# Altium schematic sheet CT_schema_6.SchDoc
size 274 x 160 mm
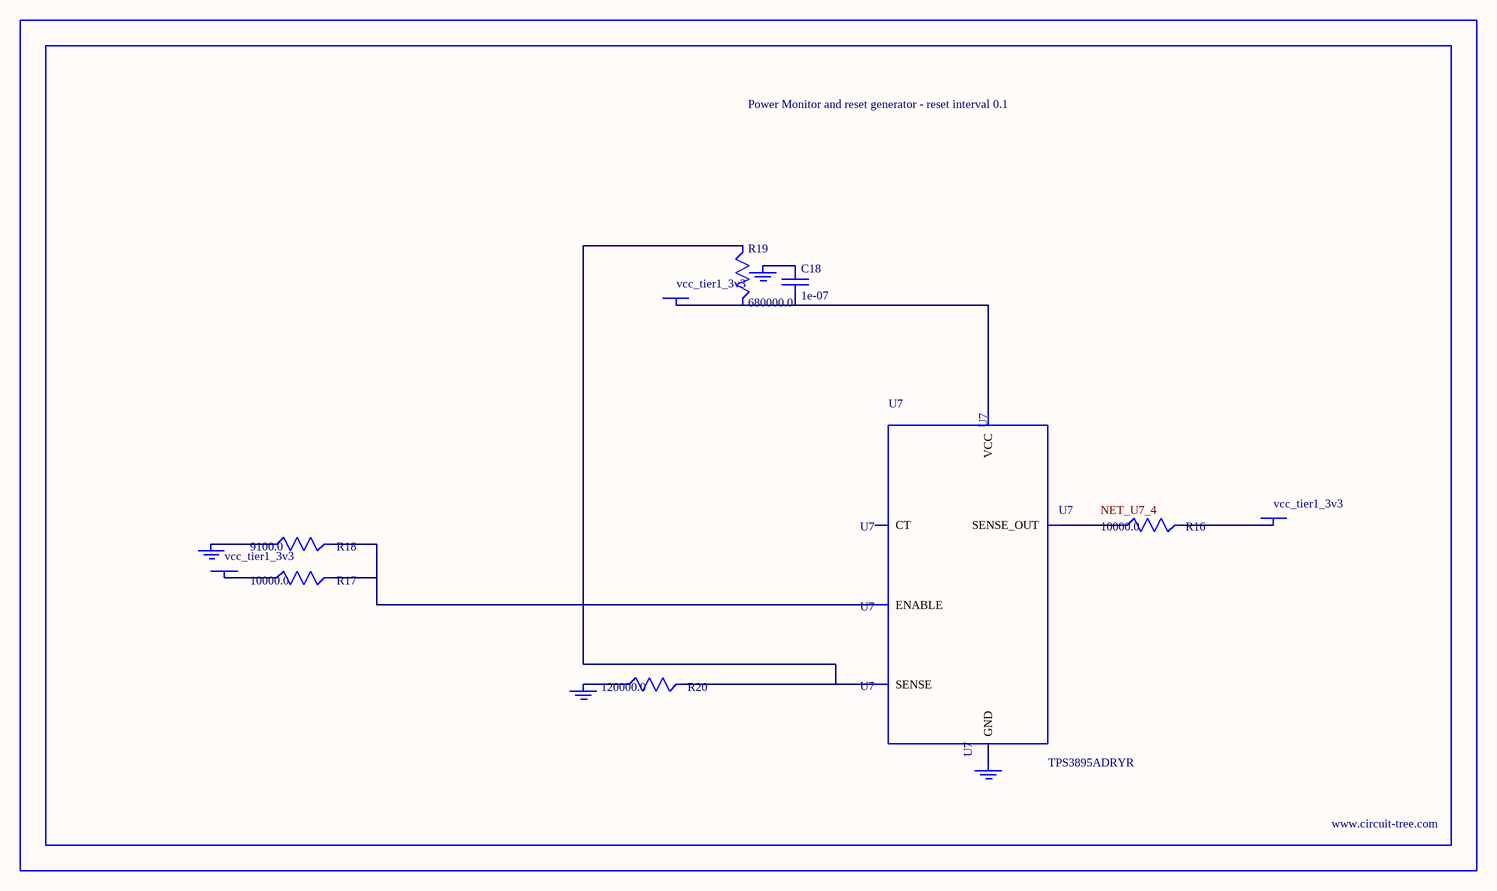
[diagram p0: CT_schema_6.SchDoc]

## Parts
BORDER5  (no value)
C18  1e-07  [C0402]
GND_INSTANCE_5_0  (no value)
GND_INSTANCE_5_1  (no value)
GND_INSTANCE_5_2  (no value)
GND_INSTANCE_5_3  (no value)
POWER_INSTANCE_5_0  vcc_tier1_3v3
POWER_INSTANCE_5_1  vcc_tier1_3v3
POWER_INSTANCE_5_2  vcc_tier1_3v3
R16  10000.0  [R0603]
R17  10000.0  [R0603]
R18  9100.0  [R0603]
R19  680000.0  [R0603]
R20  120000.0  [R0603]
U7  TPS3895ADRYR  [SON-6]

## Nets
NetC18_1: C18.1 GND_INSTANCE_5_2.0(GND)
NetC18_2: C18.2 POWER_INSTANCE_5_2.0(PWR) R19.2 U7.6(VCC)
NetGND_INSTANCE_5_0_0: GND_INSTANCE_5_0.0(GND) R18.1
NetGND_INSTANCE_5_1_0: GND_INSTANCE_5_1.0(GND) R20.1
NetGND_INSTANCE_5_3_0: GND_INSTANCE_5_3.0(GND) U7.2(GND)
NetPOWER_INSTANCE_5_0_0: POWER_INSTANCE_5_0.0(PWR) R17.1
NetPOWER_INSTANCE_5_1_0: POWER_INSTANCE_5_1.0(PWR) R16.2
NetR16_1: R16.1 U7.4(SENSE_OUT)
NetR17_2: R17.2 R18.2 U7.1(ENABLE)
NetR19_1: R19.1 R20.2 U7.3(SENSE)

Not connected (* = marked no-connect by the designer): U7 5(CT)

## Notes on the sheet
- Labels drawn without touching a wire or pin: NET_U7_4

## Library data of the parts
BORDER5 = BORDER_PAGE5
C18 = C0402C104K3RACTU
GND_INSTANCE_5_0-GND_INSTANCE_5_3 = GND
POWER_INSTANCE_5_0-POWER_INSTANCE_5_2 = PWR
R16 R17 = RC0603JR-0710KL
R18 = RC0603JR-079K1L
R19 = RC0603JR-07680KL
R20 = RC0603JR-07120KL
